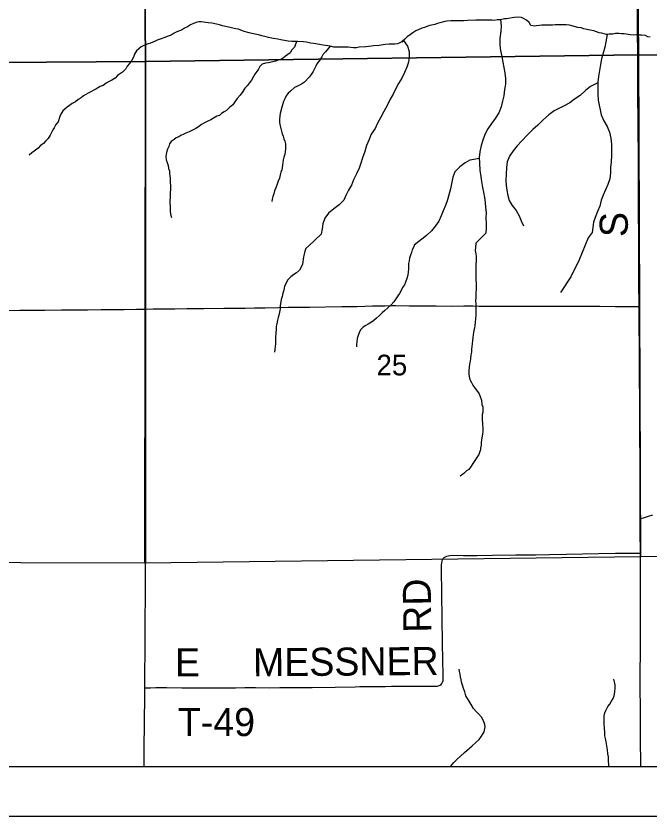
# Model space of a CAD drawing. Extents: x 0 to 34, y 0 to 22.
# Drawn here: x 22.047 to 23.331, y 9.078 to 10.698 of the extents above; entities that cross this region are included whole.
import ezdxf

# ---------------------------------------------------------------- set-up
doc = ezdxf.new("R2010")
doc.units = 0
for name, color, linetype in [('GM_X_County_Road', 7, 'Continuous'), ('GM_X_County_Road_Text', 7, 'Continuous'), ('GM_X_Minor_River', 7, 'Continuous'), ('GM_X_Section', 7, 'Continuous'), ('GM_X_Section_Text', 7, 'Continuous'), ('GM_X_Township_Road', 7, 'Continuous'), ('GM_X_Township_Road_Text', 7, 'Continuous'), ('SH_Data', 7, 'Continuous')]:
    doc.layers.add(name, color=color, linetype=linetype)

msp = doc.modelspace()

# ---------------------------------------------------------------- linework, layer by layer
at = {"layer": 'GM_X_County_Road'}
for points in [[(23.3087, 10.1096), (23.3086, 10.1172), (23.3085, 10.1512), (23.3083, 10.2038), (23.3081, 10.2441), (23.3078, 10.3093), (23.3076, 10.3744), (23.3074, 10.4208), (23.3069, 10.4645), (23.3064, 10.5577), (23.3061, 10.6228), (23.3057, 10.6663), (23.3054, 10.6973), (23.3054, 10.7344), (23.3054, 10.7399), (23.3056, 10.7424), (23.3058, 10.7444), (23.3062, 10.7482)], [(22.3099, 10.1048), (22.3098, 10.173), (22.3098, 10.288), (22.3097, 10.4807), (22.3099, 10.5801), (22.3096, 10.6485), (22.3091, 10.7138), (22.309, 10.7237)], [(22.3082, 9.3372), (22.3088, 9.4396), (22.3096, 9.5577), (22.3099, 9.6199), (22.31, 9.8188), (22.3099, 9.912), (22.3098, 10.0425), (22.3099, 10.1015), (22.3099, 10.1048)], [(23.3111, 9.6804), (23.3111, 9.7197), (23.3109, 9.7912), (23.3108, 9.8098), (23.3106, 9.8378), (23.3103, 9.9092), (23.3098, 9.9775), (23.3094, 10.021), (23.3089, 10.0788), (23.3087, 10.1096)], [(23.3117, 9.6104), (23.3111, 9.6545), (23.3111, 9.6804)], [(23.3125, 9.1775), (23.3124, 9.1856), (23.3118, 9.229), (23.3115, 9.2663), (23.3113, 9.3005), (23.3112, 9.3315), (23.3111, 9.3688), (23.3114, 9.4091), (23.3116, 9.4753), (23.3117, 9.5365), (23.3118, 9.6048), (23.3117, 9.6104)], [(22.3066, 9.1775), (22.3067, 9.1888), (22.3068, 9.204), (22.3069, 9.2115), (22.3069, 9.2127), (22.3081, 9.3215), (22.3082, 9.3372)]]:
    msp.add_lwpolyline(points, dxfattribs=at)
at = {"layer": 'GM_X_Minor_River'}
for points in [[(22.6831, 10.6376), (22.6739, 10.639), (22.6648, 10.6401), (22.6541, 10.6422), (22.6496, 10.6425), (22.6435, 10.6436), (22.6351, 10.6454), (22.629, 10.646), (22.6172, 10.6466), (22.6122, 10.6466), (22.6058, 10.6469), (22.5985, 10.6475), (22.594, 10.6479), (22.5833, 10.6504), (22.5772, 10.6514), (22.5688, 10.6528), (22.5585, 10.6546), (22.5539, 10.6561), (22.5448, 10.6582), (22.5383, 10.66), (22.5245, 10.6633), (22.5196, 10.6643), (22.5093, 10.6672), (22.4974, 10.6716), (22.4921, 10.6723), (22.486, 10.6741), (22.4806, 10.6752), (22.4654, 10.6788), (22.4593, 10.6806), (22.4532, 10.6821), (22.444, 10.6838), (22.4364, 10.6849), (22.4315, 10.6856), (22.4269, 10.6863), (22.4219, 10.6866), (22.4174, 10.6865), (22.4121, 10.6853), (22.4064, 10.6833), (22.4003, 10.6806), (22.3947, 10.6763), (22.3883, 10.6736), (22.3826, 10.6701), (22.378, 10.6685), (22.3731, 10.6662), (22.3675, 10.6634), (22.3614, 10.6599), (22.355, 10.6576), (22.3467, 10.6544), (22.3391, 10.6513), (22.333, 10.6493), (22.3278, 10.6466), (22.3198, 10.6434), (22.3149, 10.6419), (22.3058, 10.6387), (22.3005, 10.636), (22.296, 10.6317), (22.2911, 10.6279), (22.2874, 10.6214), (22.2852, 10.6149), (22.2818, 10.6087), (22.277, 10.6022), (22.2725, 10.5968), (22.2699, 10.5911), (22.2631, 10.5846), (22.2571, 10.5803), (22.2526, 10.5776), (22.2477, 10.5726), (22.2413, 10.5683), (22.2356, 10.566), (22.2296, 10.5625), (22.2236, 10.5578), (22.2175, 10.5555), (22.2088, 10.5504), (22.193, 10.5418), (22.1839, 10.5364), (22.1794, 10.5329), (22.173, 10.529), (22.1677, 10.5244), (22.1609, 10.5209), (22.1556, 10.5174), (22.1507, 10.5136), (22.1417, 10.5066), (22.138, 10.4997), (22.1358, 10.4947), (22.1325, 10.4841), (22.128, 10.4783), (22.1243, 10.4722), (22.122, 10.4676), (22.1194, 10.4622), (22.1161, 10.4573), (22.112, 10.4504), (22.1071, 10.4446), (22.1026, 10.4404), (22.097, 10.4361), (22.0921, 10.4307), (22.0842, 10.4249), (22.0793, 10.4211), (22.074, 10.4168)], [(23.3313, 10.6554), (23.3263, 10.6565), (23.3217, 10.6587), (23.3137, 10.6597), (23.3077, 10.6596), (23.3027, 10.66), (23.2981, 10.6599), (23.2909, 10.6606), (23.2783, 10.6623), (23.273, 10.6622), (23.2681, 10.6629), (23.2612, 10.6628), (23.2559, 10.662), (23.2479, 10.6615), (23.243, 10.6611), (23.2334, 10.6636), (23.2281, 10.6647), (23.2174, 10.6683), (23.2094, 10.6697), (23.2033, 10.6712), (23.1968, 10.6726), (23.1915, 10.6744), (23.185, 10.6751), (23.1728, 10.6787), (23.1682, 10.6798), (23.1613, 10.6809), (23.1389, 10.6806), (23.1336, 10.6797), (23.1271, 10.6796), (23.1191, 10.6799), (23.1119, 10.6798), (23.107, 10.679), (23.1013, 10.6785), (23.0967, 10.6781), (23.0899, 10.6792), (23.086, 10.6852), (23.081, 10.69), (23.076, 10.693), (23.0706, 10.6956), (23.0649, 10.6963), (23.0558, 10.6954), (23.0406, 10.6929), (23.0361, 10.6925), (23.0273, 10.6909), (23.0213, 10.6904), (23.0152, 10.6896), (23.0106, 10.6899), (22.9973, 10.6901), (22.992, 10.69), (22.9783, 10.6902), (22.9616, 10.6892), (22.9536, 10.6887), (22.9274, 10.6884), (22.9198, 10.6879), (22.9152, 10.6875), (22.9053, 10.6843), (22.9008, 10.6831), (22.8951, 10.6815), (22.8853, 10.6791), (22.8788, 10.6771), (22.8743, 10.6755), (22.869, 10.6735), (22.8614, 10.6704), (22.8565, 10.6681), (22.8508, 10.6646), (22.8459, 10.6611), (22.8395, 10.6564), (22.8346, 10.6518), (22.8294, 10.6468), (22.8245, 10.6441), (22.8199, 10.6421), (22.8142, 10.6413), (22.8074, 10.6412), (22.8025, 10.6411), (22.7952, 10.6407), (22.7907, 10.6402), (22.7827, 10.639), (22.7709, 10.6377), (22.766, 10.6376), (22.7554, 10.6363), (22.7417, 10.635), (22.7368, 10.6342), (22.7307, 10.6341), (22.7196, 10.6351), (22.7109, 10.6354), (22.7044, 10.6353), (22.6995, 10.6356), (22.6907, 10.6355), (22.6831, 10.6376)], [(23.0285, 10.6911), (23.0294, 10.6783), (23.0288, 10.6677), (23.0267, 10.6529), (23.0265, 10.6396), (23.0285, 10.6286), (23.0306, 10.6161), (23.033, 10.6047), (23.0371, 10.5835), (23.038, 10.5717), (23.0382, 10.5603), (23.0364, 10.5493), (23.035, 10.5367), (23.0325, 10.5257), (23.0292, 10.5146), (23.0245, 10.502), (23.0174, 10.4905), (23.0099, 10.4806), (23.0024, 10.4698), (22.9965, 10.4584), (22.9921, 10.4469), (22.9892, 10.4358), (22.9863, 10.4233), (22.9853, 10.4119), (22.9855, 10.4001), (22.9864, 10.386), (22.9881, 10.3735), (22.9898, 10.3629), (22.9914, 10.3512), (22.9935, 10.3413), (22.9959, 10.3307), (22.9972, 10.3205), (22.998, 10.3106), (22.9993, 10.3004), (22.9987, 10.2893), (22.9992, 10.2783), (22.999, 10.2685), (22.9987, 10.2582), (22.978, 10.2385)], [(23.2441, 10.6612), (23.2417, 10.6462), (23.2395, 10.6356), (23.2359, 10.623), (23.233, 10.6115), (23.2308, 10.6001), (23.2283, 10.5879), (23.2266, 10.5761), (23.2252, 10.5647), (23.2254, 10.551), (23.2252, 10.5404), (23.2261, 10.5279), (23.2277, 10.518), (23.2298, 10.5082), (23.2322, 10.498), (23.2376, 10.4863), (23.2439, 10.4746), (23.249, 10.4632), (23.2514, 10.4511), (23.2531, 10.439), (23.2532, 10.4272), (23.253, 10.4158), (23.2524, 10.4033), (23.251, 10.3915), (23.2508, 10.3805), (23.2498, 10.3687), (23.2458, 10.3572), (23.2406, 10.3461), (23.2362, 10.3354), (23.2321, 10.3255), (23.2296, 10.3133), (23.2248, 10.3022), (23.22, 10.2904), (23.2164, 10.2805), (23.2153, 10.2702), (23.214, 10.2595), (23.2059, 10.2492)], [(22.6153, 10.6466), (22.6112, 10.6352), (22.606, 10.6302), (22.6023, 10.6237), (22.5977, 10.6206), (22.5928, 10.6174), (22.5879, 10.6132), (22.5827, 10.6101), (22.5781, 10.6089), (22.5724, 10.6069), (22.5675, 10.6057), (22.558, 10.6037), (22.5527, 10.6032), (22.5459, 10.6012), (22.5406, 10.5959), (22.538, 10.5909), (22.535, 10.5859), (22.5309, 10.5809), (22.5283, 10.5759), (22.5239, 10.5683), (22.519, 10.5621), (22.5153, 10.5568), (22.5108, 10.5522), (22.5063, 10.5453), (22.5014, 10.538), (22.4951, 10.5311), (22.4902, 10.5245), (22.4861, 10.5188), (22.4793, 10.5134), (22.4737, 10.5072), (22.4688, 10.5045), (22.4635, 10.501), (22.459, 10.4971), (22.4541, 10.4952), (22.4473, 10.4913), (22.4416, 10.4878), (22.4359, 10.4854), (22.4299, 10.4827), (22.4231, 10.4784), (22.4167, 10.4738), (22.4114, 10.4707), (22.3978, 10.4637), (22.3914, 10.4613), (22.3868, 10.4593), (22.3812, 10.4566), (22.3767, 10.4539), (22.3717, 10.4515), (22.3672, 10.4481), (22.3616, 10.4442), (22.3578, 10.4392), (22.3564, 10.4342), (22.3538, 10.4289), (22.352, 10.422), (22.3509, 10.414), (22.3514, 10.4068), (22.353, 10.4015), (22.355, 10.3955), (22.3562, 10.3894), (22.3578, 10.3849), (22.3582, 10.3792), (22.359, 10.3746), (22.3595, 10.3697), (22.3598, 10.3465), (22.3595, 10.3412), (22.3592, 10.3367), (22.3592, 10.3317), (22.3589, 10.3241), (22.3586, 10.3192), (22.3591, 10.3131), (22.3592, 10.3029), (22.3601, 10.2968), (22.362, 10.2904)], [(22.6831, 10.6376), (22.6737, 10.6261), (22.6692, 10.6211), (22.6663, 10.6158), (22.6614, 10.6081), (22.6565, 10.6016), (22.6543, 10.5966), (22.6491, 10.5859), (22.6447, 10.5798), (22.6409, 10.5744), (22.6312, 10.5644), (22.6255, 10.5601), (22.6161, 10.5558), (22.6108, 10.5535), (22.6029, 10.5462), (22.598, 10.5419), (22.5943, 10.5369), (22.5917, 10.5304), (22.5887, 10.5251), (22.5854, 10.514), (22.5818, 10.5011), (22.5815, 10.4965), (22.5808, 10.4885), (22.5809, 10.4836), (22.5817, 10.4787), (22.5829, 10.473), (22.5841, 10.4677), (22.5861, 10.4597), (22.5881, 10.4548), (22.5897, 10.4495), (22.5913, 10.445), (22.5929, 10.4393), (22.593, 10.4294), (22.5923, 10.4237), (22.5912, 10.4184), (22.5898, 10.4127), (22.5883, 10.4073), (22.5876, 10.4016), (22.5866, 10.3963), (22.5852, 10.3868), (22.5837, 10.3818), (22.5819, 10.3769), (22.5808, 10.37), (22.5782, 10.3639), (22.576, 10.3574), (22.5735, 10.3502), (22.5709, 10.3444), (22.5694, 10.3383), (22.5672, 10.333), (22.5658, 10.3276), (22.5651, 10.3223)], [(22.8316, 10.6489), (22.8402, 10.6371), (22.843, 10.6265), (22.8435, 10.6155), (22.8421, 10.6048), (22.8384, 10.5949), (22.834, 10.5838), (22.8281, 10.5727), (22.8214, 10.5616), (22.8154, 10.5501), (22.8106, 10.5402), (22.805, 10.5302), (22.7987, 10.5169), (22.7921, 10.505), (22.7861, 10.4932), (22.7794, 10.4813), (22.7742, 10.4706), (22.766, 10.4591), (22.762, 10.4484), (22.7572, 10.4362), (22.7536, 10.424), (22.7488, 10.411), (22.7451, 10.4003), (22.7418, 10.3904), (22.7366, 10.3785), (22.7307, 10.3663), (22.7267, 10.356), (22.7207, 10.3457), (22.7152, 10.3349), (22.7111, 10.325), (22.7013, 10.3158), (22.6904, 10.308), (22.6799, 10.2991), (22.6728, 10.2888), (22.6687, 10.2777), (22.6674, 10.2671), (22.6652, 10.2564)], [(22.8297, 10.6454), (22.831, 10.6483)], [(23.2252, 10.5628), (23.2105, 10.5558), (23.2003, 10.5473), (23.1894, 10.5377), (23.1781, 10.5299), (23.1683, 10.5222), (23.157, 10.5167), (23.1366, 10.5062), (23.1261, 10.4981), (23.114, 10.4873), (23.1035, 10.4776), (23.0937, 10.4684), (23.0828, 10.4576), (23.0716, 10.4457), (23.0622, 10.4357), (23.0536, 10.4253), (23.0461, 10.4146), (23.0417, 10.4031), (23.0403, 10.3917), (23.0394, 10.3776), (23.0392, 10.3651), (23.0397, 10.3552), (23.0409, 10.3454), (23.043, 10.3351), (23.0454, 10.3245), (23.0516, 10.3147), (23.0597, 10.3042), (23.0663, 10.2937), (23.0703, 10.2835), (23.075, 10.2736)], [(22.9854, 10.4096), (22.9664, 10.4063), (22.9566, 10.4008), (22.946, 10.3931), (22.9359, 10.3827), (22.9318, 10.3716), (22.929, 10.3587), (22.9268, 10.3484), (22.921, 10.3263), (22.9166, 10.3148), (22.9122, 10.3038), (22.9081, 10.2935), (22.9033, 10.2831), (22.8966, 10.2732), (22.8884, 10.2632), (22.8782, 10.2539), (22.8534, 10.2341)], [(22.6652, 10.2564), (22.6402, 10.2329), (22.6342, 10.2276), (22.6319, 10.2219), (22.6308, 10.2162), (22.6293, 10.2102), (22.627, 10.1957), (22.6247, 10.1893), (22.621, 10.1836), (22.6149, 10.1783), (22.61, 10.1745), (22.6039, 10.1699), (22.5971, 10.1631), (22.5934, 10.1559), (22.5911, 10.1509), (22.5892, 10.143), (22.5873, 10.1369), (22.5858, 10.1304), (22.5843, 10.1243), (22.5832, 10.119), (22.5824, 10.1118), (22.5821, 10.105), (22.5806, 10.0981), (22.5794, 10.0924), (22.5779, 10.0875), (22.5768, 10.0822), (22.5753, 10.0746), (22.5742, 10.0693), (22.5742, 10.0632), (22.5734, 10.056), (22.5727, 10.048), (22.5723, 10.04), (22.5723, 10.0339), (22.572, 10.029), (22.5712, 10.0233), (22.5708, 10.0172)], [(23.2059, 10.2492), (23.1874, 10.2047), (23.1708, 10.1698), (23.1496, 10.1379)], [(22.8534, 10.2341), (22.8526, 10.2307), (22.8496, 10.225), (22.8477, 10.2193), (22.8462, 10.2136), (22.844, 10.2075), (22.8432, 10.2022), (22.8421, 10.1969), (22.8417, 10.1912), (22.8417, 10.1847), (22.8413, 10.1798), (22.8406, 10.1733), (22.8387, 10.1669), (22.8361, 10.1589), (22.8338, 10.1536), (22.83, 10.1483), (22.827, 10.1426), (22.824, 10.1365), (22.8206, 10.1312), (22.8164, 10.1255), (22.8119, 10.1194), (22.807, 10.113), (22.7998, 10.1073), (22.7937, 10.102), (22.7888, 10.097), (22.7835, 10.0913), (22.7771, 10.086), (22.7718, 10.0815), (22.7669, 10.0784), (22.7605, 10.0739), (22.7555, 10.0712), (22.7499, 10.0682), (22.745, 10.0625), (22.7423, 10.0564), (22.7397, 10.0511), (22.7382, 10.045), (22.7374, 10.0386), (22.7363, 10.0329), (22.7363, 10.028)], [(22.978, 10.2385), (22.9776, 10.2297), (22.9772, 10.2233), (22.9784, 10.2164), (22.9788, 10.2111), (22.9788, 10.2027), (22.9784, 10.1951), (22.978, 10.1894), (22.9784, 10.183), (22.9784, 10.1761), (22.9781, 10.1693), (22.9784, 10.1636), (22.9788, 10.1564), (22.9792, 10.1511), (22.9788, 10.1454), (22.9781, 10.1362), (22.9781, 10.1283), (22.9777, 10.1214), (22.9781, 10.1161), (22.9782, 10.0933), (22.9778, 10.0849), (22.9771, 10.0781), (22.9763, 10.0716), (22.9756, 10.0663), (22.9744, 10.0614), (22.9729, 10.0526), (22.9722, 10.0473), (22.9714, 10.0412), (22.9707, 10.034), (22.9703, 10.0291), (22.9696, 10.0234), (22.9692, 10.0173), (22.9684, 10.0116), (22.9673, 10.0044), (22.9666, 9.9991), (22.9651, 9.9938), (22.9647, 9.9865), (22.9639, 9.9805), (22.9643, 9.9729), (22.9647, 9.9679), (22.9662, 9.9618), (22.9693, 9.9557), (22.9723, 9.9504), (22.9772, 9.944), (22.9818, 9.9379), (22.9852, 9.9329), (22.9879, 9.9257), (22.9894, 9.9204), (22.9905, 9.9112), (22.9921, 9.9063), (22.9924, 9.9014), (22.9921, 9.896), (22.9913, 9.8911), (22.9913, 9.8789), (22.9917, 9.874), (22.9917, 9.8691), (22.9925, 9.8637), (22.9925, 9.8565), (22.9914, 9.8512), (22.9899, 9.8398), (22.9891, 9.8345), (22.9888, 9.8288), (22.988, 9.8227), (22.9875, 9.819)], [(22.9875, 9.819), (22.9873, 9.8178), (22.9846, 9.8098), (22.9801, 9.8041), (22.9759, 9.798), (22.9722, 9.7916), (22.9688, 9.7863), (22.9642, 9.7794), (22.9593, 9.7768), (22.9536, 9.7718), (22.9464, 9.7662)], [(22.9736, 9.2956), (22.9691, 9.3036), (22.9649, 9.3101), (22.9611, 9.3154), (22.9581, 9.3211), (22.9558, 9.3291), (22.9535, 9.3356), (22.952, 9.3405), (22.9497, 9.347), (22.9485, 9.3531), (22.9474, 9.3595), (22.9466, 9.3652), (22.9455, 9.3702), (22.9447, 9.3751)], [(23.2476, 9.1775), (23.2476, 9.1816), (23.2468, 9.1895), (23.2468, 9.1975), (23.2456, 9.2036), (23.2449, 9.2116), (23.2433, 9.22), (23.2422, 9.2279), (23.2407, 9.2348), (23.2395, 9.2397), (23.2391, 9.2462), (23.2387, 9.2564), (23.2383, 9.2644), (23.2383, 9.2728), (23.2379, 9.2804), (23.2391, 9.2865), (23.2421, 9.2929), (23.2455, 9.2994), (23.2493, 9.3043), (23.2527, 9.3104), (23.2565, 9.3153), (23.258, 9.321), (23.2595, 9.3282), (23.2606, 9.3377), (23.2602, 9.3434), (23.2587, 9.3495), (23.2579, 9.3548)], [(22.9268, 9.1775), (22.934, 9.1859), (22.9404, 9.1927), (22.9469, 9.1988), (22.9552, 9.206), (22.9711, 9.2196), (22.9783, 9.2265), (22.9851, 9.2325), (22.99, 9.239), (22.9949, 9.2481), (22.9968, 9.258), (22.9964, 9.2629), (22.9937, 9.2701), (22.9899, 9.2777), (22.9839, 9.2842), (22.9786, 9.2892), (22.9736, 9.2956)]]:
    msp.add_lwpolyline(points, dxfattribs=at)
at = {"layer": 'GM_X_Section'}
for points in [[(23.2983, 11.6235), (23.3079, 10.6196), (22.3097, 10.6062), (22.3015, 11.617)], [(23.2983, 11.6235), (24.0077, 11.623), (24.0161, 10.618), (23.3079, 10.6196)], [(22.3015, 11.617), (22.3097, 10.6062), (21.3072, 10.5992), (21.2987, 11.6032)], [(22.3097, 10.6062), (23.3079, 10.6196), (23.3119, 9.6024), (22.308, 9.5897)], [(23.3079, 10.6196), (24.0161, 10.618), (24.0154, 9.6102), (23.3119, 9.6024)], [(21.3072, 10.5992), (22.3097, 10.6062), (22.308, 9.5897), (21.3039, 9.5926)]]:
    msp.add_lwpolyline(points, close=True, dxfattribs=at)
at = {"layer": 'GM_X_Township_Road'}
for points in [[(21.8073, 10.1001), (21.8258, 10.1003), (21.8534, 10.1002), (21.931, 10.1007), (21.987, 10.1012), (22.0242, 10.1016), (22.0553, 10.1021), (22.105, 10.1025), (22.1392, 10.103), (22.1702, 10.1034), (22.192, 10.1034), (22.2198, 10.1036), (22.2663, 10.1041), (22.2911, 10.1043), (22.3099, 10.1048)], [(22.3099, 10.1048), (22.3251, 10.1051), (22.3468, 10.1052), (22.3686, 10.1053), (22.3934, 10.1056), (22.4276, 10.1057), (22.468, 10.1062), (22.5114, 10.1065), (22.53, 10.107), (22.5516, 10.1074), (22.5795, 10.1079), (22.5982, 10.1083), (22.6137, 10.1085), (22.6417, 10.1087), (22.7069, 10.1096), (22.7379, 10.1101), (22.769, 10.1109), (22.7938, 10.1113), (22.8093, 10.1116), (22.8155, 10.1116), (22.8435, 10.1112), (22.8715, 10.1113), (22.8866, 10.1113), (22.8982, 10.1111), (22.932, 10.1108), (22.9538, 10.111), (22.9721, 10.1109), (22.9851, 10.1107), (22.9971, 10.1106), (23.0217, 10.1103), (23.0434, 10.1103), (23.0714, 10.1104), (23.1549, 10.1104), (23.1828, 10.1103), (23.2294, 10.1103), (23.2604, 10.1099), (23.2822, 10.1098), (23.2977, 10.1099), (23.3057, 10.1097), (23.3087, 10.1096)], [(23.3111, 9.6804), (23.3147, 9.6812), (23.3177, 9.6819), (23.3219, 9.683), (23.3281, 9.6848), (23.3368, 9.688)], [(23.3117, 9.6104), (23.3111, 9.6545), (23.3111, 9.6804)], [(22.3082, 9.3372), (22.3115, 9.3373), (22.3194, 9.3375), (22.3301, 9.3378), (22.3518, 9.3377), (22.3829, 9.3375), (22.4171, 9.3374), (22.4482, 9.3372), (22.4637, 9.3372), (22.4761, 9.3373), (22.4917, 9.3375), (22.5103, 9.3377), (22.532, 9.3377), (22.56, 9.3375), (22.5817, 9.3376), (22.619, 9.3378), (22.647, 9.3382), (22.6936, 9.3388), (22.7338, 9.3394), (22.7435, 9.3396), (22.7527, 9.3397), (22.7644, 9.3398), (22.7777, 9.3399), (22.7876, 9.3399), (22.7951, 9.3399), (22.8075, 9.3403), (22.823, 9.3406), (22.8665, 9.3407), (22.8882, 9.3405), (22.8977, 9.3406), (22.9009, 9.3409), (22.904, 9.3418), (22.906, 9.3426), (22.9078, 9.3439), (22.9094, 9.3457), (22.911, 9.3486), (22.9119, 9.3518), (22.9123, 9.3549), (22.9124, 9.3581), (22.9124, 9.3675), (22.9117, 9.3892), (22.9109, 9.4327), (22.9102, 9.4731), (22.9092, 9.5322), (22.9086, 9.5726), (22.9086, 9.585), (22.9092, 9.591), (22.9099, 9.5939), (22.911, 9.5967), (22.9124, 9.5992), (22.9144, 9.6014), (22.9168, 9.6029), (22.9195, 9.6041), (22.9224, 9.6049), (22.9254, 9.6053), (22.9315, 9.6057), (22.9532, 9.6056), (22.9812, 9.6054), (23.0123, 9.6057), (23.0589, 9.6065), (23.0993, 9.607), (23.1273, 9.6075), (23.1615, 9.6082), (23.2268, 9.6096), (23.2609, 9.6101), (23.2857, 9.6104), (23.3089, 9.6104), (23.3117, 9.6104)]]:
    msp.add_lwpolyline(points, dxfattribs=at)
at = {"layer": 'SH_Data'}
for p, q in [((17.8579, 9.1775), (24.6579, 9.1775)), ((17.7579, 9.0775), (24.7579, 9.0775))]:
    msp.add_line(p, q, dxfattribs=at)

# ---------------------------------------------------------------- texts
at = {"layer": 'GM_X_County_Road_Text'}
msp.add_text('S', height=0.0568, rotation=90, dxfattribs=at).set_placement((23.2859, 10.2506))
at = {"layer": 'GM_X_Section_Text'}
msp.add_text('25', height=0.04186, rotation=0, dxfattribs=at).set_placement((22.7771, 9.9703))
at = {"layer": 'GM_X_Township_Road_Text'}
for s, height, rotation, p in [('RD', 0.05682, 90.975, (22.8885, 9.4493)), ('MESSNER', 0.05682, 0.4417, (22.5273, 9.3605)), ('E', 0.0568, 0, (22.3691, 9.3605)), ('T-49', 0.05682, 0, (22.375, 9.2395))]:
    msp.add_text(s, height=height, rotation=rotation, dxfattribs=at).set_placement(p)

doc.saveas('drawing.dxf')
